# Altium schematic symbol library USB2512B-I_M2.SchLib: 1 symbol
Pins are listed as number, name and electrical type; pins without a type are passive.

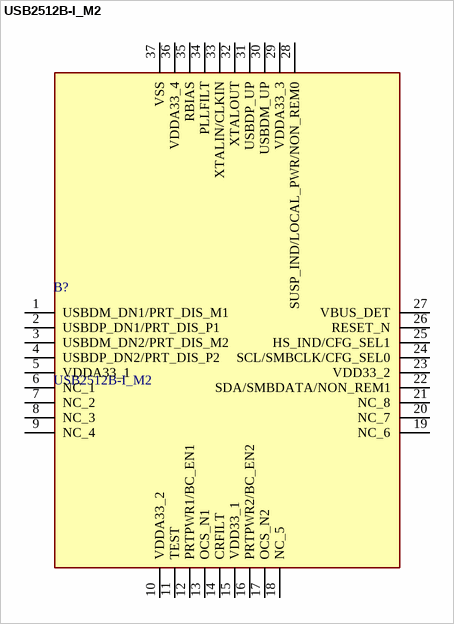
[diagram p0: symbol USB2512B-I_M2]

## USB2512B-I_M2
designator B?
Microchip USB2512B-I/M2, USB Controller, USB 2.0, 3.3 V, 36-Pin SQFN; Geometry.Height: 1mm
footprint QFN50P600X600X100-37N-D
pins: 1 USBDM_DN1/PRT_DIS_M1, 2 USBDP_DN1/PRT_DIS_P1, 3 USBDM_DN2/PRT_DIS_M2, 4 USBDP_DN2/PRT_DIS_P2, 5 VDDA33_1, 6 NC_1, 7 NC_2, 8 NC_3, 9 NC_4, 10 VDDA33_2, 11 TEST, 12 PRTPWR1/BC_EN1, 13 OCS_N1, 14 CRFILT, 15 VDD33_1, 16 PRTPWR2/BC_EN2, 17 OCS_N2, 18 NC_5, 19 NC_6, 20 NC_7, 21 NC_8, 22 SDA/SMBDATA/NON_REM1, 23 VDD33_2, 24 SCL/SMBCLK/CFG_SEL0, 25 HS_IND/CFG_SEL1, 26 RESET_N, 27 VBUS_DET, 28 SUSP_IND/LOCAL_PWR/NON_REM0, 29 VDDA33_3, 30 USBDM_UP, 31 USBDP_UP, 32 XTALOUT, 33 XTALIN/CLKIN, 34 PLLFILT, 35 RBIAS, 36 VDDA33_4, 37 VSS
